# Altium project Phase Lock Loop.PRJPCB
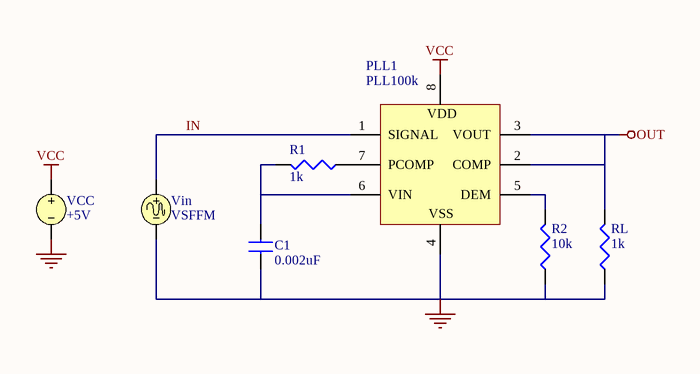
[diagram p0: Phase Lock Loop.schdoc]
1 sheet, 7 parts. Net scope: global (net labels, ports and power ports of the same name join across sheets).

## Sheet Phase Lock Loop.schdoc: Phase Lock Loop
size A4; Organization: Altium Limited; Address1: L3, 12a Rodborough Rd; Address2: Frenchs Forest; Address3: NSW; Address4: Australia 2086; DocumentNumber: 1; SheetNumber: 1; SheetTotal: 1

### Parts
C1  0.002uF
PLL1  PLL100k
R1  1k
R2  10k
RL  1k
VCC  +5V
Vin  VSFFM

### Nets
GND: C1.2 PLL1.4(VSS) R2.2(BOT) RL.2(BOT) VCC.2 Vin.2
OUT: PLL1.2(COMP) PLL1.3(VOUT) RL.1(TOP)
VCC: PLL1.8(VDD) VCC.1
IN: PLL1.1(SIGNAL) Vin.1
NetC1_1: C1.1 PLL1.6(VIN) R1.1(TOP)
NetPLL1_5: PLL1.5(DEM) R2.1(TOP)
NetPLL1_7: PLL1.7(PCOMP) R1.2(BOT)

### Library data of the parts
C1 = CAP: Capacitor
PLL1 = PLL100k: Generic Phase Locked Loop
R1 R2 RL = RES: Resistor
VCC = VSRC: Voltage Source
Vin = VSFFM: Frequency-Modulated Sinusoidal Voltage Source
